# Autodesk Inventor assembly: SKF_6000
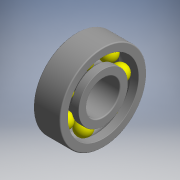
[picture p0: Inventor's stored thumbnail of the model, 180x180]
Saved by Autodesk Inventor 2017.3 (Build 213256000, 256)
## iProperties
Category: PARTsolutions
Company: SKF
Part Number: SKF_6000
Catalog Web Link: www.cadenas.de
Description: BB1_001_101-Deep groove ball bearings
Vendor: SKF
Document SubType Name: Assembly
Designer: partserver
Manufacturer: SKF
Mass: 19 g
Surface Area: 28.5617 cm^2
Volume: 2.35526 cm^3
Density: 8.06705 g/cm^3
Title: SKF_6000
Author: Cadenas PARTsolutions
Comments: Deep groove ball bearings
PSOL_IDENT_0: {$CADENAS_DATA\23d-libs\skf\bearings_units_and_housings\ball_bearings\deep_groove_ball_bearings\bb1_
PSOL_IDENT_1: 001_101.prj},163 {VTYP=3D},{NB=SKF_6000},{LINA=SKF_6000},{NN=BB1_001_101},{DATE=18.06.2021 07:30:58}
PSOL_IDENT_2: ,{GEOMDATE=16.06.2021 12:48:44},{VERSION=},{LINEID=5840},{WBVAR=},{WBNUMERIC=}  {NB=SKF_6000},{LINA=
PSOL_IDENT_3: SKF_6000},{KT=DUMMY},{DESIGNATION=6000},{R12=0.30},{DD=10.000},{D=26.000},{B=8.000},{C=},{CX=},{CXX=
PSOL_IDENT_4: },{CA=0.000},{XXVARIANT=},{XXDESIGN=Single row},{XXSEALING=No seals},{DESIGN=dgbb1},{DESIGNIR=dgbb1}
PSOL_IDENT_5: ,{VARIANT=},{DD1=14.80},{DD2=},{DD2X=},{DD2A=0.00},{D1=21.20},{D1X=MIN},{D2=22.6},{D2A=22.60},{D3=},
PSOL_IDENT_6: {D3X=},{D3A=0.000},{D4=},{HH=MIN},{BB=MIN},{BBX=},{BBA=0.000},{FF=},{R0MAX=MIN},{R0=MIN},{PITCH=17.8
PSOL_IDENT_7: 0},{DW=4.762},{DDAMIN=12.000},{DDAMAX=MIN},{DDBMIN=MIN},{DDBMAX=MIN},{DBMIN=MIN},{DAMAX=24.000},{BBA
PSOL_IDENT_8: MIN=MIN},{CAMAX=MIN},{RAMAX=0.300},{LOAD1=4.750},{LOAD2=1.960},{LOAD3=0.083},{SPEED1=67000},{SPEED2=
PSOL_IDENT_9: 40000},{KR=0.025},{F0=12.000},{Z=7},{II=1},{MASS=0.019},{BEARING=6000},{RING=},{HELP=2.400},{HELP2=1
PSOL_IDENT_10: .700},{DD1ALG=7.400},{YALG=7.400},{PITCH1=17.800},{DW1=4.762},{YALG1=10.600},{HALG1=2.400},{SH=7.400
PSOL_IDENT_11: },{CU=0.648},{HALG=2.4},{B1=0},{SHIELDHELP=1},{D4A=0.000},{FFA=0.000},{RS1=}
NB: SKF_6000
NN: BB1_001_101
NT: Deep groove ball bearings
NBSYN: SKF_$DESIGNATION.
LINA: SKF_6000
CATALOG: SKF
DESIGNATION: 6000
R12: 0.3
DD: 10
D: 26
B: 8
D2: 22.6
LOAD1: 4.75
LOAD2: 1.96
LOAD3: 0.083
SPEED1: 67000
SPEED2: 40000
BEARING: 6000
SUPPLIER: SKF
ARTICLENO: SKF_6000
BOMINFO: SKF_6000
CREATOR: CADENAS GmbH
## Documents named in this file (5)
- e:\temp\worker_39\temp\exporttempdir_6628_70_DRJUy\format_0\SKF_6000.iam
- e:\temp\worker_39\temp\exporttempdir_6628_70_DRJUy\format_0\SKF_6000_PART1.ipt
- e:\temp\worker_39\temp\exporttempdir_6628_70_DRJUy\format_0\SKF_6000_PART2.ipt
- e:\temp\worker_39\temp\exporttempdir_6628_70_DRJUy\format_0\SKF_6000_PART3.ipt
- e:\temp\worker_39\temp\exporttempdir_6628_70_DRJUy\format_0\SKF_6000_PART4.ipt
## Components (16 placed, 4 different names)
1. SKF_6000_PART1:1
2. SKF_6000_PART2:1
3. SKF_6000_PART3:1
4. SKF_6000_PART3:2
5. SKF_6000_PART3:3
6. SKF_6000_PART3:4
7. SKF_6000_PART3:5
8. SKF_6000_PART3:6
9. SKF_6000_PART3:7
10. SKF_6000_PART4:1
11. SKF_6000_PART4:2
12. SKF_6000_PART4:3
13. SKF_6000_PART4:4
14. SKF_6000_PART4:5
15. SKF_6000_PART4:6
16. SKF_6000_PART4:7
